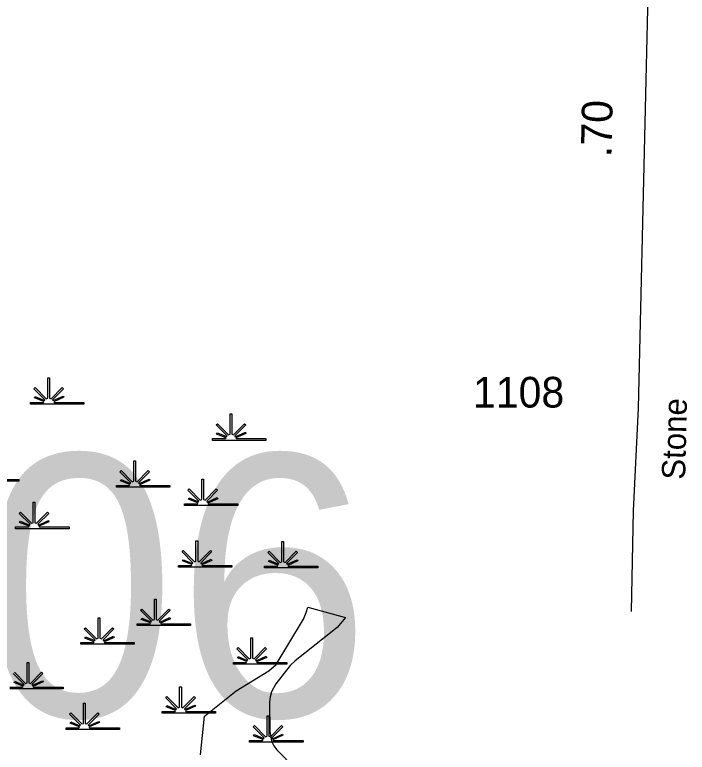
# Model space of a CAD drawing. Extents: x 2220236 to 2384410, y 720751 to 894131.
# Drawn here: x 2248711 to 2251450, y 733523 to 736527 of the extents above; entities that cross this region are included whole.
import ezdxf

# ---------------------------------------------------------------- set-up
doc = ezdxf.new("R2010")
doc.units = 0
doc.layers.add('Default', color=7, linetype='Continuous')

msp = doc.modelspace()

# ---------------------------------------------------------------- linework, layer by layer
at = {"layer": 'Default'}
for points in [[(2251316.9, 737772.4), (2251250.4, 734924.7), (2251229.4, 734507), (2251221.7, 734095.9)], [(2248605.6, 734634.3), (2248726.6, 734634.2), (2248726.6, 734627.1), (2248509.1, 734627.1)], [(2249466.7, 733512.5), (2249483.1, 733669.5), (2249612.1, 733773.9), (2249746.2, 733855.4), (2249775.9, 733880.8), (2249886.4, 734065.6), (2249897.9, 734092.3), (2249904.5, 734113.9), (2250057.4, 734072.3), (2250024.4, 734032), (2249852.4, 733896.2), (2249832.5, 733876), (2249774.5, 733801.7), (2249756.2, 733768.9), (2249750.7, 733748.6), (2249748.8, 733727.8), (2249749.8, 733608.7), (2249757.2, 733568.7), (2249765.8, 733549.7), (2249777.9, 733532.6), (2249852.2, 733457.9)], [(2248709.4, 733849.2), (2248754.7, 733803.7), (2248761, 733806.1), (2248761, 733889.2), (2248768.3, 733889.2), (2248768.2, 733806.1), (2248774.6, 733803.7), (2248819.9, 733849.2), (2248825, 733844.1), (2248780.6, 733799.6), (2248782.6, 733796), (2248823.5, 733814.6), (2248825.9, 733809.5), (2248784.9, 733791.7), (2248786.6, 733788.8), (2248907.6, 733788.7), (2248907.6, 733781.6), (2248690.1, 733781.6)], [(2248709.4, 733812.4), (2248747.1, 733796.7), (2248748.7, 733799.6), (2248704.3, 733844.1)], [(2248690.1, 733788.7), (2248742.7, 733788.8), (2248744.7, 733792.4), (2248706.5, 733807.2)]]:
    msp.add_lwpolyline(points, dxfattribs=at)
for points in [[(2248774.6, 734948.3), (2248827.2, 734948.3), (2248829.2, 734951.9), (2248790.9, 734966.8), (2248793.8, 734972), (2248831.6, 734956.2), (2248833.2, 734959.1), (2248788.7, 735003.6), (2248793.9, 735008.8), (2248839.1, 734963.3), (2248845.5, 734965.7), (2248845.5, 735048.8), (2248852.7, 735048.8), (2248852.7, 734965.7), (2248859, 734963.3), (2248904.3, 735008.8), (2248909.5, 735003.6), (2248865, 734959.1), (2248867, 734955.5), (2248907.9, 734974.1), (2248910.4, 734969.1), (2248869.4, 734951.3), (2248871, 734948.3), (2248992.1, 734948.3), (2248992.1, 734941.2), (2248774.6, 734941.2)], [(2249516.6, 734800.9), (2249569.3, 734801), (2249571.3, 734804.6), (2249533, 734819.4), (2249535.9, 734824.6), (2249573.7, 734808.9), (2249575.3, 734811.7), (2249530.8, 734856.3), (2249536, 734861.4), (2249581.2, 734815.9), (2249587.6, 734818.3), (2249587.6, 734901.4), (2249594.8, 734901.4), (2249594.8, 734818.3), (2249601.1, 734815.9), (2249646.4, 734861.4), (2249651.6, 734856.3), (2249607.1, 734811.7), (2249609.1, 734808.1), (2249650, 734826.7), (2249652.5, 734821.7), (2249611.5, 734803.9), (2249613.1, 734801), (2249734.1, 734800.9), (2249734.1, 734793.8), (2249516.6, 734793.8)], [(2249124.5, 734610.1), (2249177.1, 734610.1), (2249179.1, 734613.7), (2249140.9, 734628.6), (2249143.8, 734633.8), (2249181.5, 734618), (2249183.1, 734620.9), (2249138.7, 734665.4), (2249143.8, 734670.6), (2249189.1, 734625.1), (2249195.4, 734627.5), (2249195.4, 734710.6), (2249202.7, 734710.6), (2249202.6, 734627.5), (2249209, 734625.1), (2249254.3, 734670.6), (2249259.4, 734665.4), (2249215, 734620.9), (2249217, 734617.3), (2249257.9, 734635.9), (2249260.3, 734630.9), (2249219.3, 734613.1), (2249221, 734610.1), (2249342, 734610.1), (2249342, 734603), (2249124.5, 734603)], [(2249402, 734535.2), (2249454.6, 734535.2), (2249456.6, 734538.9), (2249418.4, 734553.7), (2249421.3, 734558.9), (2249459, 734543.1), (2249460.6, 734546), (2249416.2, 734590.6), (2249421.3, 734595.7), (2249466.6, 734550.2), (2249472.9, 734552.6), (2249472.9, 734635.7), (2249480.2, 734635.7), (2249480.2, 734552.6), (2249486.5, 734550.2), (2249531.8, 734595.7), (2249536.9, 734590.6), (2249492.5, 734546), (2249494.5, 734542.4), (2249535.4, 734561), (2249537.8, 734556), (2249496.9, 734538.2), (2249498.5, 734535.2), (2249619.5, 734535.2), (2249619.5, 734528.1), (2249402, 734528.1)], [(2248714.2, 734441), (2248766.9, 734441), (2248768.9, 734444.6), (2248730.6, 734459.5), (2248733.5, 734464.7), (2248771.2, 734448.9), (2248772.8, 734451.8), (2248728.4, 734496.3), (2248733.5, 734501.5), (2248778.8, 734456), (2248785.1, 734458.4), (2248785.1, 734541.5), (2248792.4, 734541.5), (2248792.4, 734458.4), (2248798.7, 734456), (2248844, 734501.5), (2248849.1, 734496.3), (2248804.7, 734451.8), (2248806.7, 734448.2), (2248847.6, 734466.8), (2248850.1, 734461.8), (2248809.1, 734444), (2248810.7, 734441), (2248931.7, 734441), (2248931.7, 734433.9), (2248714.2, 734433.9)], [(2249377.9, 734283.9), (2249430.5, 734284), (2249432.5, 734287.6), (2249394.3, 734302.5), (2249397.2, 734307.6), (2249434.9, 734291.9), (2249436.5, 734294.8), (2249392.1, 734339.3), (2249397.2, 734344.5), (2249442.5, 734299), (2249448.8, 734301.4), (2249448.8, 734384.4), (2249456.1, 734384.4), (2249456, 734301.4), (2249462.4, 734299), (2249507.7, 734344.5), (2249512.8, 734339.3), (2249468.4, 734294.8), (2249470.4, 734291.2), (2249511.3, 734309.8), (2249513.7, 734304.7), (2249472.7, 734286.9), (2249474.3, 734284), (2249595.4, 734283.9), (2249595.4, 734276.8), (2249377.9, 734276.8)], [(2249727.8, 734281.5), (2249780.4, 734281.6), (2249782.4, 734285.2), (2249744.2, 734300), (2249747.1, 734305.2), (2249784.8, 734289.5), (2249786.4, 734292.4), (2249742, 734336.9), (2249747.1, 734342), (2249792.4, 734296.6), (2249798.7, 734298.9), (2249798.7, 734382), (2249806, 734382), (2249805.9, 734298.9), (2249812.3, 734296.6), (2249857.6, 734342), (2249862.7, 734336.9), (2249818.3, 734292.4), (2249820.3, 734288.8), (2249861.2, 734307.4), (2249863.6, 734302.3), (2249822.7, 734284.5), (2249824.3, 734281.6), (2249945.3, 734281.5), (2249945.3, 734274.4), (2249727.8, 734274.4)], [(2249208.9, 734046), (2249261.6, 734046.1), (2249263.6, 734049.7), (2249225.3, 734064.5), (2249228.2, 734069.7), (2249266, 734054), (2249267.6, 734056.8), (2249223.1, 734101.4), (2249228.3, 734106.5), (2249273.5, 734061), (2249279.9, 734063.4), (2249279.9, 734146.5), (2249287.1, 734146.5), (2249287.1, 734063.4), (2249293.4, 734061), (2249338.7, 734106.5), (2249343.9, 734101.4), (2249299.4, 734056.8), (2249301.4, 734053.2), (2249342.3, 734071.8), (2249344.8, 734066.8), (2249303.8, 734049), (2249305.4, 734046.1), (2249426.5, 734046), (2249426.5, 734038.9), (2249208.9, 734038.9)], [(2248979.7, 733969.9), (2249032.3, 733970), (2249034.3, 733973.6), (2248996.1, 733988.4), (2248999, 733993.6), (2249036.7, 733977.9), (2249038.3, 733980.7), (2248993.9, 734025.3), (2248999, 734030.4), (2249044.3, 733984.9), (2249050.6, 733987.3), (2249050.6, 734070.4), (2249057.9, 734070.4), (2249057.8, 733987.3), (2249064.2, 733984.9), (2249109.5, 734030.4), (2249114.6, 734025.3), (2249070.2, 733980.7), (2249072.2, 733977.1), (2249113.1, 733995.7), (2249115.5, 733990.7), (2249074.5, 733972.9), (2249076.2, 733970), (2249197.2, 733969.9), (2249197.2, 733962.8), (2248979.7, 733962.8)], [(2249601.1, 733889), (2249653.7, 733889), (2249655.7, 733892.6), (2249617.5, 733907.5), (2249620.4, 733912.7), (2249658.1, 733896.9), (2249659.7, 733899.8), (2249615.3, 733944.4), (2249620.4, 733949.5), (2249665.7, 733904), (2249672, 733906.4), (2249672, 733989.5), (2249679.3, 733989.5), (2249679.3, 733906.4), (2249685.6, 733904), (2249730.9, 733949.5), (2249736, 733944.4), (2249691.6, 733899.8), (2249693.6, 733896.2), (2249734.5, 733914.8), (2249736.9, 733909.8), (2249696, 733892), (2249697.6, 733889), (2249818.6, 733889), (2249818.6, 733881.9), (2249601.1, 733881.9)], [(2249311.5, 733689.7), (2249364.1, 733689.7), (2249366.1, 733693.4), (2249327.9, 733708.2), (2249330.8, 733713.4), (2249368.5, 733697.6), (2249370.1, 733700.5), (2249325.7, 733745.1), (2249330.8, 733750.2), (2249376.1, 733704.7), (2249382.4, 733707.1), (2249382.4, 733790.2), (2249389.7, 733790.2), (2249389.7, 733707.1), (2249396, 733704.7), (2249441.3, 733750.2), (2249446.4, 733745.1), (2249402, 733700.5), (2249404, 733696.9), (2249444.9, 733715.5), (2249447.3, 733710.5), (2249406.4, 733692.7), (2249408, 733689.7), (2249529, 733689.7), (2249529, 733682.6), (2249311.5, 733682.6)], [(2248919.4, 733623.2), (2248972, 733623.3), (2248974, 733626.9), (2248935.7, 733641.8), (2248938.6, 733646.9), (2248976.4, 733631.2), (2248978, 733634.1), (2248933.5, 733678.6), (2248938.7, 733683.8), (2248983.9, 733638.3), (2248990.3, 733640.7), (2248990.3, 733723.7), (2248997.5, 733723.7), (2248997.5, 733640.7), (2249003.8, 733638.3), (2249049.1, 733683.8), (2249054.3, 733678.6), (2249009.8, 733634.1), (2249011.8, 733630.5), (2249052.7, 733649.1), (2249055.2, 733644), (2249014.2, 733626.2), (2249015.8, 733623.3), (2249136.9, 733623.2), (2249136.9, 733616.1), (2248919.4, 733616.1)], [(2249667.5, 733571.3), (2249720.1, 733571.4), (2249722.1, 733575), (2249683.9, 733589.8), (2249686.8, 733595), (2249724.5, 733579.3), (2249726.1, 733582.1), (2249681.7, 733626.7), (2249686.8, 733631.8), (2249732.1, 733586.3), (2249738.4, 733588.7), (2249738.4, 733671.8), (2249745.6, 733671.8), (2249745.6, 733588.7), (2249752, 733586.3), (2249797.3, 733631.8), (2249802.4, 733626.7), (2249758, 733582.1), (2249760, 733578.5), (2249800.9, 733597.1), (2249803.3, 733592.1), (2249762.3, 733574.3), (2249763.9, 733571.4), (2249885, 733571.3), (2249885, 733564.2), (2249667.5, 733564.2)]]:
    msp.add_lwpolyline(points, close=True, dxfattribs=at)

# ---------------------------------------------------------------- texts
for s, height, p in [('.70', 125, (2251141.1, 735946.2)), ('Stone', 95, (2251441.3, 734632.7))]:
    msp.add_text(s, height=height, rotation=88.6257, dxfattribs=at).set_placement(p)
for s, height, p in [('1108', 125, (2250577.3, 734927.3)), ('106', 1066.27, (2247781.5, 733669))]:
    msp.add_text(s, height=height, dxfattribs=at).set_placement(p)

doc.saveas('drawing.dxf')
